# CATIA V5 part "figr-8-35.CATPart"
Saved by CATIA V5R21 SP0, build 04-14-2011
Part number: Part1
Bounding box of the stored display mesh (mm): x -75 to 75, y -75 to 75, z 0 to 20
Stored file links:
  D:\CATIA V5R21 E-RESOURCES\CATIA-V5R21\catia-v5r21-prt\c08-catia-v5r20-prt\c08-catia-v5r21-figr-8-35.CATPart
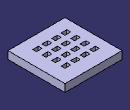
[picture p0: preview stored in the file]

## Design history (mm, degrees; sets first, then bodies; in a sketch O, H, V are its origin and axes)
Body1 (main body)
  Sketch1 on xy-plane, origin (0, 0, 0), H (1, 0, 0), V (0, 1, 0)
    line L1 (-75, 75) -> (75, 75)
    line L2 (75, 75) -> (75, -75)
    line L3 (75, -75) -> (-75, -75)
    line L4 (-75, -75) -> (-75, 75)
    axis line L5 (75, -75) -> (-75, 75)
    length L3 = 150
    length L2 = 150
    horizontal: L1 H, L3 H
    vertical: L2 V, L4 V
    midpoint: O L5
  Pad1: profile Sketch1, direction (0, 0, 1), length 20
  Sketch2 on face of Pad1, origin (0, 0, 20), H (1, 0, 0), V (0, 1, 0)
    line L1 (25, 40) -> (40, 40)
    line L2 (40, 40) -> (40, 30)
    line L3 (40, 30) -> (25, 30)
    line L4 (25, 30) -> (25, 40)
    reference projected line E1 (75, -75) -> (75, 75) from edge [face of Pad1 | face of Pad1]
    reference projected line E2 (75, 75) -> (-75, 75) from edge [face of Pad1 | face of Pad1]
    length L3 = 15
    length L4 = 10
    distance L2 E1 = 35
    distance L1 E2 = 35
    horizontal: L1 H, L3 H
    vertical: L2 V, L4 V
  Pocket1: profile Sketch2, direction (0, 0, -1), through (limit type 3)
  RectPattern1: of Pocket1, direction 1 instances 4, spacing -25, along end face of Pad1, direction 2 instances 4, spacing 25, along end face of Pad1 reversed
